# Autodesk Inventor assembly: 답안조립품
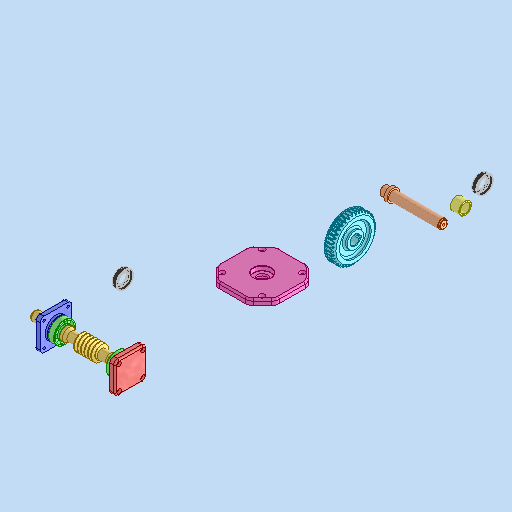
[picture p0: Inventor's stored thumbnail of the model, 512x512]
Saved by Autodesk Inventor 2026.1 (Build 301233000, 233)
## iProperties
Created: 2026-02
Part Number: 답안조립품
Document SubType Name: Assembly
Designer: PC-30
Author: PC-30
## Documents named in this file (11)
- C:\Users\PC-30\Desktop\760203V1012\답안조립품.iam
- C:\Users\PC-30\Desktop\760203V1012\본체.ipt
- C:\Users\PC-30\Desktop\760203V1012\테이퍼 롤러 베어링 30203.ipt
- C:\Users\PC-30\Desktop\760203V1012\앞커버.ipt
- C:\Users\PC-30\Desktop\760203V1012\뒷커버.ipt
- C:\Users\PC-30\Desktop\760203V1012\웜 샤프트.ipt
- C:\Users\PC-30\Desktop\760203V1012\웜 휠 커버.ipt
- C:\Users\PC-30\Desktop\760203V1012\웜 휠.ipt
- C:\Users\PC-30\Desktop\760203V1012\축.ipt
- C:\Users\PC-30\Desktop\760203V1012\칼라.ipt
- C:\Users\PC-30\Desktop\760203V1012\오일 실 17 32 8.ipt
